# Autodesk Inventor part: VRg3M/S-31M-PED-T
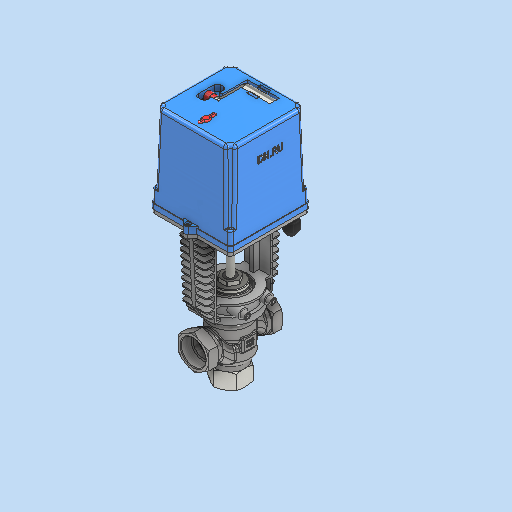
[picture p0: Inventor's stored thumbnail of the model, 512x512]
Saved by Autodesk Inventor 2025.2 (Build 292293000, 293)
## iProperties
Created: 2026-04
Part Number: VRg3M/S-31M-PED-T
Material: Типовые
Description: D230-11266
Document SubType Name: Modeling
Designer: DN.RU
Mass: 3700 g
Surface Area: 2289.62 cm^2
Volume: 2565.02 cm^3
Density: 1.44249 g/cm^3
Appearance: По умолчанию
Company: DN.RU
Title: Клапан регулирующий трехходовой Ду32 Ру25
Author: DN.RU
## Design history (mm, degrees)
derived "Сборка.iam"
node "Твердое тело1"
node "Деталь 1.ipt:1"
node "Деталь 2.ipt:1"
node "Деталь 3.ipt:1"
node "AS 1420 - метрическая M5 x 10:1"
node "AS 1420 - метрическая M5 x 10:2"
node "AS 1427 H - метрическая M3 x 8:1"
node "AS 1427 H - метрическая M3 x 8:2"
node "AS 1421 засверленный конец - метрическая M10 x 12 засверленн"
node "AS 1421 засверленный конец - метрическая M10 x 12 засверленн"
